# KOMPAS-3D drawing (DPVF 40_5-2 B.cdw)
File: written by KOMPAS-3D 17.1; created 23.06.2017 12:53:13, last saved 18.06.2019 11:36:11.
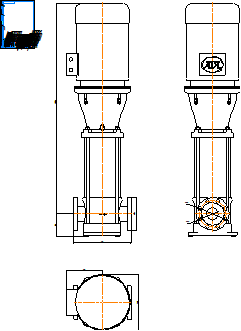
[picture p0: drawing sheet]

Sheet 1: A4, portrait

Title block, sheet 1: name: DPVF 40_5-2 B; material: Внимание! Данный продукт является объектом авторского права ООО «Торговый Дом АДЛ». / Запрещается изменение, копирование, распространение / (в том числе путем копирования на другие сайты и ресурсы в Интернете) / или любое иное использование информации и объектов без предварительного / согласия правообладателя (ООО «Торговый Дом АДЛ»).; scale: 1:1; sheets: 1; organisation: ООО "Торговый дом АДЛ"; sheet format: A4; stored path: C:\Клочков АВ\Насосы\DP PAMS\DPVF 40\Компас 2d\DPVF 40_5-2 B.cdw

Views: Спереди 1
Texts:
  Клочков АВ
  ООО АДЛ ГРУПП
Dimensions and other numbers on the sheet: 365; 223; 350; 209,6; 1312,5; 140; 168,1; 76,2; 1:1; 1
